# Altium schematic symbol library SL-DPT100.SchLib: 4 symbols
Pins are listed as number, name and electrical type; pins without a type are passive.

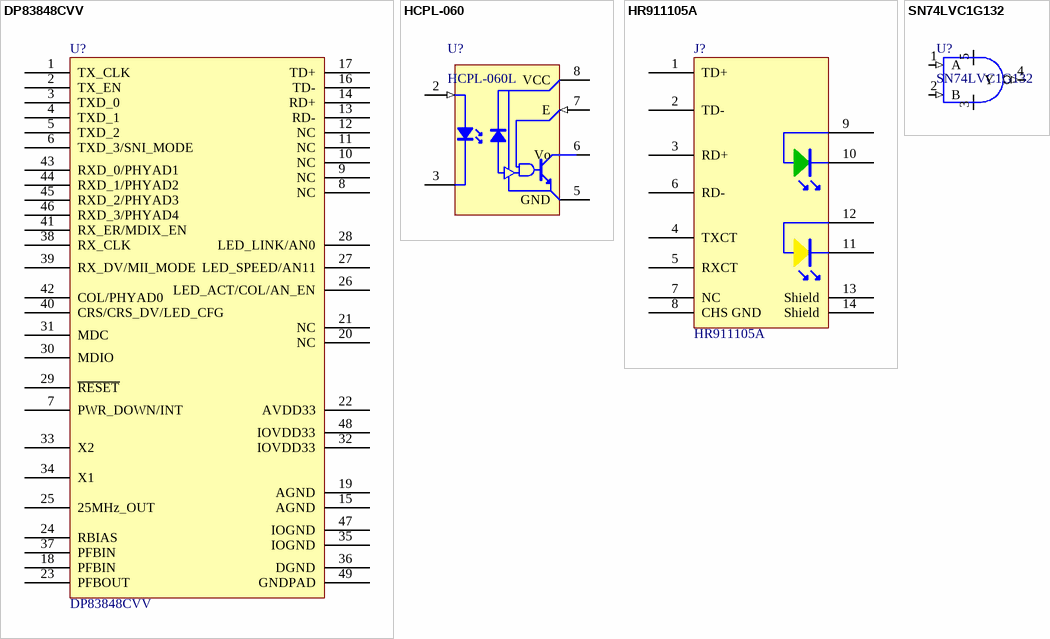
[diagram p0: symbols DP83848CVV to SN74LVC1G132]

## DP83848CVV
designator U?
pins: 1 TX_CLK, 2 TX_EN, 3 TXD_0, 4 TXD_1, 5 TXD_2, 6 TXD_3/SNI_MODE, 7 PWR_DOWN/INT, 8 NC, 9 NC, 10 NC, 11 NC, 12 NC, 13 RD-, 14 RD+, 15 AGND, 16 TD-, 17 TD+, 18 PFBIN, 19 AGND, 20 NC, 21 NC, 22 AVDD33, 23 PFBOUT, 24 RBIAS, 25 25MHz_OUT, 26 LED_ACT/COL/AN_EN, 27 LED_SPEED/AN11, 28 LED_LINK/AN0, 29 ~{RESET}, 30 MDIO, 31 MDC, 32 IOVDD33, 33 X2, 34 X1, 35 IOGND, 36 DGND, 37 PFBIN, 38 RX_CLK, 39 RX_DV/MII_MODE, 40 CRS/CRS_DV/LED_CFG, 41 RX_ER/MDIX_EN, 42 COL/PHYAD0, 43 RXD_0/PHYAD1, 44 RXD_1/PHYAD2, 45 RXD_2/PHYAD3, 46 RXD_3/PHYAD4, 47 IOGND, 48 IOVDD33, 49 GNDPAD (power)

## HCPL-060
designator U?, comment HCPL-060L
footprint SO8_M (8-Pin Small Outline Integrated Circuit 1.27 mm Pitch, IPC Low Density)
pins: 2 + (in), 3 -, 5 GND (power), 6 Vo (oc), 7 E (in), 8 VCC (power)

## HR911105A
designator J?
pins: 1 TD+, 2 TD-, 3 RD+, 4 TXCT, 5 RXCT, 6 RD-, 7 NC, 8 CHS GND, 9, 10, 11, 12, 13 Shield (power), 14 Shield (power)

## SN74LVC1G132
designator U?
footprint SOT23-5
pins: 1 A (in), 2 B (in), 3 GND (power), 4 Y (out), 5 VCC (power)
